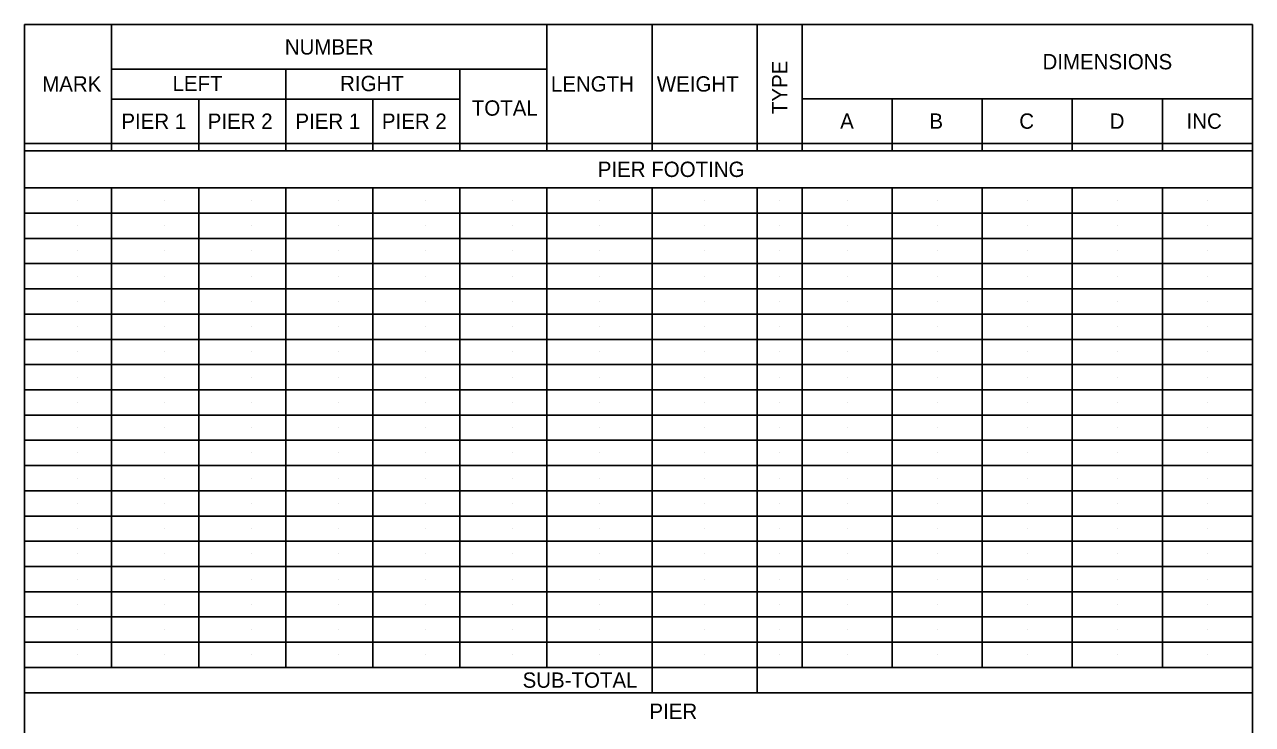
# Model space of a CAD drawing. Extents: x -16.6 to 33.3, y -8.6 to 39.2.
# Drawn here: x 17.16 to 30.79, y 31.42 to 39.18 of the extents above; entities that cross this region are included whole.
import ezdxf

# ---------------------------------------------------------------- set-up
doc = ezdxf.new("R2010")
doc.units = 0
doc.layers.add('BR_X_Beam_Centerline', color=7, linetype='Continuous')

msp = doc.modelspace()

# ---------------------------------------------------------------- linework, layer by layer
at = {"layer": 'BR_X_Beam_Centerline'}
for p, q in [((17.157, 39.182), (30.791, 39.183)), ((17.157, 25.759), (17.157, 39.183)), ((18.124, 37.782), (18.124, 39.182)), ((22.957, 37.782), (22.957, 39.182)), ((24.124, 37.783), (24.124, 39.182)), ((25.291, 37.783), (25.291, 39.182)), ((25.791, 37.783), (25.791, 39.182)), ((30.791, 25.759), (30.791, 39.183)), ((18.124, 38.688), (22.957, 38.688)), ((20.057, 37.782), (20.057, 38.688)), ((21.991, 37.782), (21.991, 38.688)), ((18.124, 38.356), (21.991, 38.356)), ((19.091, 37.782), (19.091, 38.356)), ((21.024, 37.782), (21.024, 38.356)), ((25.791, 38.359), (30.791, 38.359)), ((26.791, 37.782), (26.791, 38.359)), ((27.791, 37.782), (27.791, 38.359)), ((28.791, 37.782), (28.791, 38.359)), ((29.791, 37.782), (29.791, 38.359)), ((29.791, 37.782), (29.791, 38.359)), ((18.603, 38.111), (18.603, 38.111)), ((19.569, 38.111), (19.569, 38.111)), ((20.536, 38.111), (20.536, 38.111)), ((21.503, 38.111), (21.503, 38.111)), ((17.157, 37.865), (30.791, 37.865)), ((17.157, 37.782), (30.791, 37.782)), ((24.374, 37.577), (24.374, 37.577)), ((17.157, 37.371), (30.791, 37.371)), ((18.124, 32.051), (18.124, 37.371)), ((19.091, 32.051), (19.091, 37.371)), ((20.057, 32.051), (20.057, 37.371)), ((21.024, 32.051), (21.024, 37.371)), ((21.991, 32.051), (21.991, 37.371)), ((22.957, 32.051), (22.957, 37.371)), ((24.124, 31.771), (24.124, 37.371)), ((25.291, 31.771), (25.291, 37.371)), ((25.791, 32.051), (25.791, 37.371)), ((26.791, 32.051), (26.791, 37.371)), ((27.791, 32.051), (27.791, 37.371)), ((28.791, 32.051), (28.791, 37.371)), ((29.791, 32.051), (29.791, 37.371)), ((29.791, 32.051), (29.791, 37.371)), ((17.741, 37.231), (17.741, 37.231)), ((18.707, 37.231), (18.707, 37.231)), ((19.674, 37.231), (19.674, 37.231)), ((20.641, 37.231), (20.641, 37.231)), ((21.607, 37.231), (21.607, 37.231)), ((22.574, 37.231), (22.574, 37.231)), ((23.541, 37.231), (23.541, 37.231)), ((24.707, 37.231), (24.707, 37.231)), ((25.541, 37.231), (25.541, 37.231)), ((26.291, 37.231), (26.291, 37.231)), ((27.291, 37.231), (27.291, 37.231)), ((28.291, 37.231), (28.291, 37.231)), ((29.291, 37.231), (29.291, 37.231)), ((30.291, 37.231), (30.291, 37.231)), ((17.157, 37.091), (30.791, 37.091)), ((17.741, 36.951), (17.741, 36.951)), ((18.707, 36.951), (18.707, 36.951)), ((19.674, 36.951), (19.674, 36.951)), ((20.641, 36.951), (20.641, 36.951)), ((21.607, 36.951), (21.607, 36.951)), ((22.574, 36.951), (22.574, 36.951)), ((23.541, 36.951), (23.541, 36.951)), ((24.707, 36.951), (24.707, 36.951)), ((25.541, 36.951), (25.541, 36.951)), ((26.291, 36.951), (26.291, 36.951)), ((27.291, 36.951), (27.291, 36.951)), ((28.291, 36.951), (28.291, 36.951)), ((29.291, 36.951), (29.291, 36.951)), ((30.291, 36.951), (30.291, 36.951)), ((17.157, 36.811), (30.791, 36.811)), ((17.741, 36.671), (17.741, 36.671)), ((18.707, 36.671), (18.707, 36.671)), ((19.674, 36.671), (19.674, 36.671)), ((20.641, 36.671), (20.641, 36.671)), ((21.607, 36.671), (21.607, 36.671)), ((22.574, 36.671), (22.574, 36.671)), ((23.541, 36.671), (23.541, 36.671)), ((24.707, 36.671), (24.707, 36.671)), ((25.541, 36.671), (25.541, 36.671)), ((26.291, 36.671), (26.291, 36.671)), ((27.291, 36.671), (27.291, 36.671)), ((28.291, 36.671), (28.291, 36.671)), ((29.291, 36.671), (29.291, 36.671)), ((30.291, 36.671), (30.291, 36.671)), ((17.157, 36.531), (30.791, 36.531)), ((17.741, 36.391), (17.741, 36.391)), ((18.707, 36.391), (18.707, 36.391)), ((19.674, 36.391), (19.674, 36.391)), ((20.641, 36.391), (20.641, 36.391)), ((21.607, 36.391), (21.607, 36.391)), ((22.574, 36.391), (22.574, 36.391)), ((23.541, 36.391), (23.541, 36.391)), ((24.707, 36.391), (24.707, 36.391)), ((25.541, 36.391), (25.541, 36.391)), ((26.291, 36.391), (26.291, 36.391)), ((27.291, 36.391), (27.291, 36.391)), ((28.291, 36.391), (28.291, 36.391)), ((29.291, 36.391), (29.291, 36.391)), ((30.291, 36.391), (30.291, 36.391)), ((17.157, 36.251), (30.791, 36.251)), ((17.741, 36.111), (17.741, 36.111)), ((18.707, 36.111), (18.707, 36.111)), ((19.674, 36.111), (19.674, 36.111)), ((20.641, 36.111), (20.641, 36.111)), ((21.607, 36.111), (21.607, 36.111)), ((22.574, 36.111), (22.574, 36.111)), ((23.541, 36.111), (23.541, 36.111)), ((24.707, 36.111), (24.707, 36.111)), ((25.541, 36.111), (25.541, 36.111)), ((26.291, 36.111), (26.291, 36.111)), ((27.291, 36.111), (27.291, 36.111)), ((28.291, 36.111), (28.291, 36.111)), ((29.291, 36.111), (29.291, 36.111)), ((30.291, 36.111), (30.291, 36.111)), ((17.157, 35.971), (30.791, 35.971)), ((17.741, 35.831), (17.741, 35.831)), ((18.707, 35.831), (18.707, 35.831)), ((19.674, 35.831), (19.674, 35.831)), ((20.641, 35.831), (20.641, 35.831)), ((21.607, 35.831), (21.607, 35.831)), ((22.574, 35.831), (22.574, 35.831)), ((23.541, 35.831), (23.541, 35.831)), ((24.707, 35.831), (24.707, 35.831)), ((25.541, 35.831), (25.541, 35.831)), ((26.291, 35.831), (26.291, 35.831)), ((27.291, 35.831), (27.291, 35.831)), ((28.291, 35.831), (28.291, 35.831)), ((29.291, 35.831), (29.291, 35.831)), ((30.291, 35.831), (30.291, 35.831)), ((17.157, 35.691), (30.791, 35.691)), ((17.741, 35.551), (17.741, 35.551)), ((18.707, 35.551), (18.707, 35.551)), ((19.674, 35.551), (19.674, 35.551)), ((20.641, 35.551), (20.641, 35.551)), ((21.607, 35.551), (21.607, 35.551)), ((22.574, 35.551), (22.574, 35.551)), ((23.541, 35.551), (23.541, 35.551)), ((24.707, 35.551), (24.707, 35.551)), ((25.541, 35.551), (25.541, 35.551)), ((26.291, 35.551), (26.291, 35.551)), ((27.291, 35.551), (27.291, 35.551)), ((28.291, 35.551), (28.291, 35.551)), ((29.291, 35.551), (29.291, 35.551)), ((30.291, 35.551), (30.291, 35.551)), ((17.157, 35.411), (30.791, 35.411)), ((17.741, 35.271), (17.741, 35.271)), ((18.707, 35.271), (18.707, 35.271)), ((19.674, 35.271), (19.674, 35.271)), ((20.641, 35.271), (20.641, 35.271)), ((21.607, 35.271), (21.607, 35.271)), ((22.574, 35.271), (22.574, 35.271)), ((23.541, 35.271), (23.541, 35.271)), ((24.707, 35.271), (24.707, 35.271)), ((25.541, 35.271), (25.541, 35.271)), ((26.291, 35.271), (26.291, 35.271)), ((27.291, 35.271), (27.291, 35.271)), ((28.291, 35.271), (28.291, 35.271)), ((29.291, 35.271), (29.291, 35.271)), ((30.291, 35.271), (30.291, 35.271)), ((17.157, 35.131), (30.791, 35.131)), ((17.741, 34.991), (17.741, 34.991)), ((18.707, 34.991), (18.707, 34.991)), ((19.674, 34.991), (19.674, 34.991)), ((20.641, 34.991), (20.641, 34.991)), ((21.607, 34.991), (21.607, 34.991)), ((22.574, 34.991), (22.574, 34.991)), ((23.541, 34.991), (23.541, 34.991)), ((24.707, 34.991), (24.707, 34.991)), ((25.541, 34.991), (25.541, 34.991)), ((26.291, 34.991), (26.291, 34.991)), ((27.291, 34.991), (27.291, 34.991)), ((28.291, 34.991), (28.291, 34.991)), ((29.291, 34.991), (29.291, 34.991)), ((30.291, 34.991), (30.291, 34.991)), ((17.157, 34.851), (30.791, 34.851)), ((17.741, 34.711), (17.741, 34.711)), ((18.707, 34.711), (18.707, 34.711)), ((19.674, 34.711), (19.674, 34.711)), ((20.641, 34.711), (20.641, 34.711)), ((21.607, 34.711), (21.607, 34.711)), ((22.574, 34.711), (22.574, 34.711)), ((23.541, 34.711), (23.541, 34.711)), ((24.707, 34.711), (24.707, 34.711)), ((25.541, 34.711), (25.541, 34.711)), ((26.291, 34.711), (26.291, 34.711)), ((27.291, 34.711), (27.291, 34.711)), ((28.291, 34.711), (28.291, 34.711)), ((29.291, 34.711), (29.291, 34.711)), ((30.291, 34.711), (30.291, 34.711)), ((17.157, 34.571), (30.791, 34.571)), ((17.741, 34.431), (17.741, 34.431)), ((18.707, 34.431), (18.707, 34.431)), ((19.674, 34.431), (19.674, 34.431)), ((20.641, 34.431), (20.641, 34.431)), ((21.607, 34.431), (21.607, 34.431)), ((22.574, 34.431), (22.574, 34.431)), ((23.541, 34.431), (23.541, 34.431)), ((24.707, 34.431), (24.707, 34.431)), ((25.541, 34.431), (25.541, 34.431)), ((26.291, 34.431), (26.291, 34.431)), ((27.291, 34.431), (27.291, 34.431)), ((28.291, 34.431), (28.291, 34.431)), ((29.291, 34.431), (29.291, 34.431)), ((30.291, 34.431), (30.291, 34.431)), ((17.157, 34.291), (30.791, 34.291)), ((17.741, 34.151), (17.741, 34.151)), ((18.707, 34.151), (18.707, 34.151)), ((19.674, 34.151), (19.674, 34.151)), ((20.641, 34.151), (20.641, 34.151)), ((21.607, 34.151), (21.607, 34.151)), ((22.574, 34.151), (22.574, 34.151)), ((23.541, 34.151), (23.541, 34.151)), ((24.707, 34.151), (24.707, 34.151)), ((25.541, 34.151), (25.541, 34.151)), ((26.291, 34.151), (26.291, 34.151)), ((27.291, 34.151), (27.291, 34.151)), ((28.291, 34.151), (28.291, 34.151)), ((29.291, 34.151), (29.291, 34.151)), ((30.291, 34.151), (30.291, 34.151)), ((17.157, 34.011), (30.791, 34.011)), ((17.741, 33.871), (17.741, 33.871)), ((18.707, 33.871), (18.707, 33.871)), ((19.674, 33.871), (19.674, 33.871)), ((20.641, 33.871), (20.641, 33.871)), ((21.607, 33.871), (21.607, 33.871)), ((22.574, 33.871), (22.574, 33.871)), ((23.541, 33.871), (23.541, 33.871)), ((24.707, 33.871), (24.707, 33.871)), ((25.541, 33.871), (25.541, 33.871)), ((26.291, 33.871), (26.291, 33.871)), ((27.291, 33.871), (27.291, 33.871)), ((28.291, 33.871), (28.291, 33.871)), ((29.291, 33.871), (29.291, 33.871)), ((30.291, 33.871), (30.291, 33.871)), ((17.157, 33.731), (30.791, 33.731)), ((17.741, 33.591), (17.741, 33.591)), ((18.707, 33.591), (18.707, 33.591)), ((19.674, 33.591), (19.674, 33.591)), ((20.641, 33.591), (20.641, 33.591)), ((21.607, 33.591), (21.607, 33.591)), ((22.574, 33.591), (22.574, 33.591)), ((23.541, 33.591), (23.541, 33.591)), ((24.707, 33.591), (24.707, 33.591)), ((25.541, 33.591), (25.541, 33.591)), ((26.291, 33.591), (26.291, 33.591)), ((27.291, 33.591), (27.291, 33.591)), ((28.291, 33.591), (28.291, 33.591)), ((29.291, 33.591), (29.291, 33.591)), ((30.291, 33.591), (30.291, 33.591)), ((17.157, 33.451), (30.791, 33.451)), ((17.741, 33.311), (17.741, 33.311)), ((18.707, 33.311), (18.707, 33.311)), ((19.674, 33.311), (19.674, 33.311)), ((20.641, 33.311), (20.641, 33.311)), ((21.607, 33.311), (21.607, 33.311)), ((22.574, 33.311), (22.574, 33.311)), ((23.541, 33.311), (23.541, 33.311)), ((24.707, 33.311), (24.707, 33.311)), ((25.541, 33.311), (25.541, 33.311)), ((26.291, 33.311), (26.291, 33.311)), ((27.291, 33.311), (27.291, 33.311)), ((28.291, 33.311), (28.291, 33.311)), ((29.291, 33.311), (29.291, 33.311)), ((30.291, 33.311), (30.291, 33.311)), ((17.157, 33.171), (30.791, 33.171)), ((17.741, 33.031), (17.741, 33.031)), ((18.707, 33.031), (18.707, 33.031)), ((19.674, 33.031), (19.674, 33.031)), ((20.641, 33.031), (20.641, 33.031)), ((21.607, 33.031), (21.607, 33.031)), ((22.574, 33.031), (22.574, 33.031)), ((23.541, 33.031), (23.541, 33.031)), ((24.707, 33.031), (24.707, 33.031)), ((25.541, 33.031), (25.541, 33.031)), ((26.291, 33.031), (26.291, 33.031)), ((27.291, 33.031), (27.291, 33.031)), ((28.291, 33.031), (28.291, 33.031)), ((29.291, 33.031), (29.291, 33.031)), ((30.291, 33.031), (30.291, 33.031)), ((17.157, 32.891), (30.791, 32.891)), ((17.741, 32.751), (17.741, 32.751)), ((18.707, 32.751), (18.707, 32.751)), ((19.674, 32.751), (19.674, 32.751)), ((20.641, 32.751), (20.641, 32.751)), ((21.607, 32.751), (21.607, 32.751)), ((22.574, 32.751), (22.574, 32.751)), ((23.541, 32.751), (23.541, 32.751)), ((24.707, 32.751), (24.707, 32.751)), ((25.541, 32.751), (25.541, 32.751)), ((26.291, 32.751), (26.291, 32.751)), ((27.291, 32.751), (27.291, 32.751)), ((28.291, 32.751), (28.291, 32.751)), ((29.291, 32.751), (29.291, 32.751)), ((30.291, 32.751), (30.291, 32.751)), ((17.157, 32.611), (30.791, 32.611)), ((17.741, 32.471), (17.741, 32.471)), ((18.707, 32.471), (18.707, 32.471)), ((19.674, 32.471), (19.674, 32.471)), ((20.641, 32.471), (20.641, 32.471)), ((21.607, 32.471), (21.607, 32.471)), ((22.574, 32.471), (22.574, 32.471)), ((23.541, 32.471), (23.541, 32.471)), ((24.707, 32.471), (24.707, 32.471)), ((25.541, 32.471), (25.541, 32.471)), ((26.291, 32.471), (26.291, 32.471)), ((27.291, 32.471), (27.291, 32.471)), ((28.291, 32.471), (28.291, 32.471)), ((29.291, 32.471), (29.291, 32.471)), ((30.291, 32.471), (30.291, 32.471)), ((17.157, 32.331), (30.791, 32.331)), ((17.741, 32.191), (17.741, 32.191)), ((18.707, 32.191), (18.707, 32.191)), ((19.674, 32.191), (19.674, 32.191)), ((20.641, 32.191), (20.641, 32.191)), ((21.607, 32.191), (21.607, 32.191)), ((22.574, 32.191), (22.574, 32.191)), ((23.541, 32.191), (23.541, 32.191)), ((24.707, 32.191), (24.707, 32.191)), ((25.541, 32.191), (25.541, 32.191)), ((26.291, 32.191), (26.291, 32.191)), ((27.291, 32.191), (27.291, 32.191)), ((28.291, 32.191), (28.291, 32.191)), ((29.291, 32.191), (29.291, 32.191)), ((30.291, 32.191), (30.291, 32.191)), ((17.157, 32.051), (30.791, 32.051)), ((17.157, 31.771), (30.791, 31.771)), ((24.374, 31.565), (24.374, 31.565))]:
    msp.add_line(p, q, dxfattribs=at)

# ---------------------------------------------------------------- texts
for s, p in [('NUMBER', (20.047, 38.85)), ('DIMENSIONS', (28.46, 38.686)), ('MARK', (17.353, 38.439)), ('LEFT', (18.8, 38.444)), ('RIGHT', (20.661, 38.444)), ('LENGTH', (23.001, 38.439)), ('WEIGHT', (24.177, 38.439)), ('TOTAL', (22.123, 38.172)), ('PIER 1', (18.232, 38.026)), ('PIER 2', (19.191, 38.026)), ('PIER 1', (20.165, 38.026)), ('PIER 2', (21.125, 38.026)), ('A', (26.213, 38.027)), ('B', (27.204, 38.027)), ('C', (28.202, 38.027)), ('D', (29.206, 38.027)), ('INC', (30.059, 38.027)), ('PIER FOOTING', (23.522, 37.492)), ('SUB-TOTAL', (22.687, 31.826)), ('PIER', (24.095, 31.48))]:
    msp.add_text(s, height=0.17, dxfattribs=at).set_placement(p)
msp.add_text('TYPE', height=0.17, rotation=90, dxfattribs=at).set_placement((25.626, 38.189))

doc.saveas('drawing.dxf')
